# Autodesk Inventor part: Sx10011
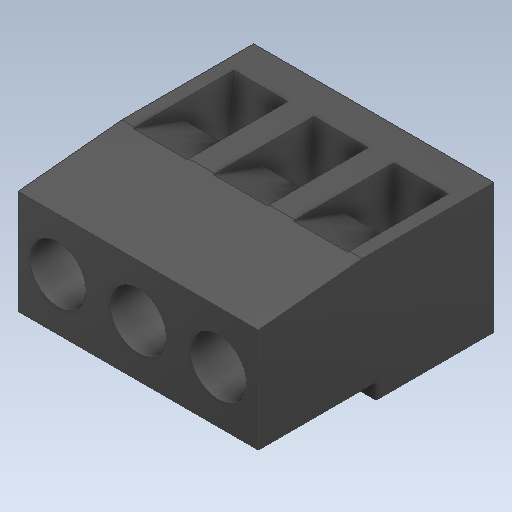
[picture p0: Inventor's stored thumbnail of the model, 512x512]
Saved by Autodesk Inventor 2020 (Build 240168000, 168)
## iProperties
Created: 2021-02
Part Number: Sx10011
Material: Generico
Document SubType Name: Modeling
Designer: zambolin
Density: 1 g/cm^3
Appearance: Default
Author: zambolin
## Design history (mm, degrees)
feature "Solido2"
node "Solido1"
